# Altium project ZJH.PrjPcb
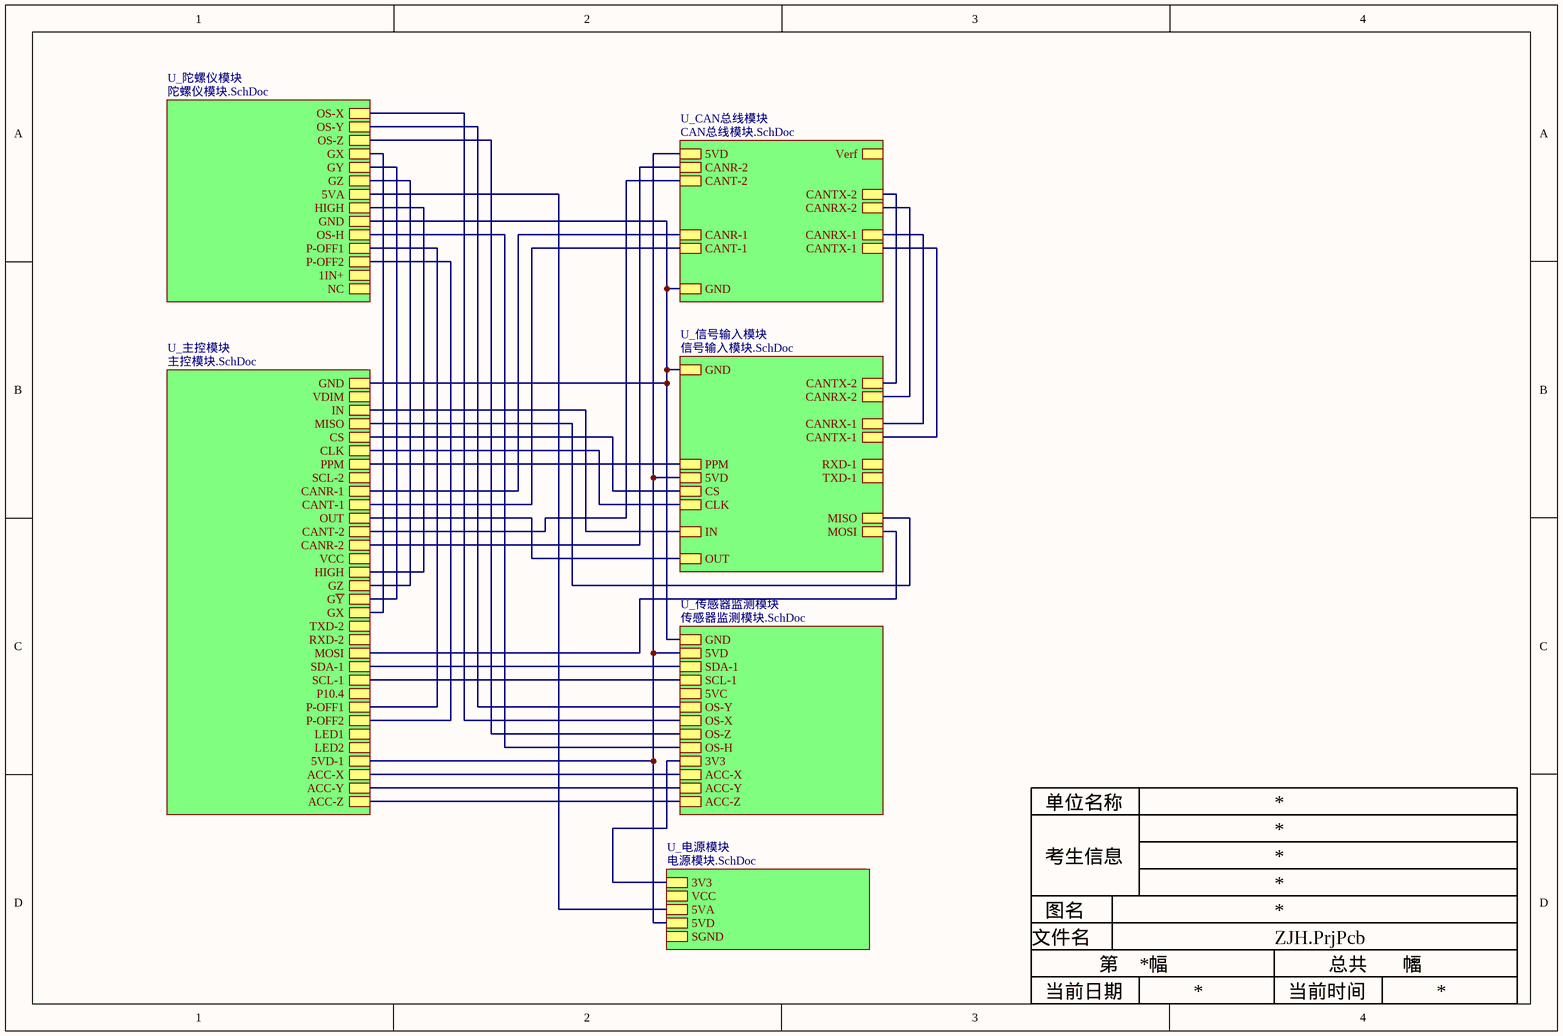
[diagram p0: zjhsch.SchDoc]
7 sheets, 110 parts. Net scope: hierarchical (ports join the sheet entries above them; power ports are global).
Board file: zjhpcb.PcbDoc
Sheets:
  zjhsch.SchDoc
    U_主控模块 = 主控模块.SchDoc
    U_传感器监测模块 = 传感器监测模块.SchDoc
    U_陀螺仪模块 = 陀螺仪模块.SchDoc
    U_CAN总线模块 = CAN总线模块.SchDoc
    U_信号输入模块 = 信号输入模块.SchDoc
    U_电源模块 = 电源模块.SchDoc

## Sheet zjhsch.SchDoc
size A4

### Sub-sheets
U_CAN总线模块 = CAN总线模块.SchDoc: 5VD, CANR-2, CANT-2, CANTX-2, CANRX-2, Verf, CANTX-1, CANRX-1, GND, CANR-1, CANT-1
U_主控模块 = 主控模块.SchDoc: 5VD-1, LED2, P10.4, SCL-1, SDA-1, LED1, P-OFF2, P-OFF1, RXD-2, MOSI, TXD-2, GX, G~{Y}, GZ, HIGH, ACC-X, ACC-Y, ACC-Z, VCC, CANT-1, CANT-2, OUT, CANR-1, SCL-2, PPM, CS, CLK, MISO, IN, GND, VDIM, CANR-2
U_传感器监测模块 = 传感器监测模块.SchDoc: GND, 5VD, SDA-1, SCL-1, 5VC, OS-Y, OS-X, OS-Z, OS-H, 3V3, ACC-Z, ACC-Y, ACC-X
U_信号输入模块 = 信号输入模块.SchDoc: OUT, MOSI, IN, MISO, CLK, CS, 5VD, PPM, TXD-1, RXD-1, CANTX-1, CANRX-1, CANRX-2, CANTX-2, GND
U_电源模块 = 电源模块.SchDoc: 3V3, VCC, 5VA, 5VD, SGND
U_陀螺仪模块 = 陀螺仪模块.SchDoc: 5VA, OS-X, 1IN+, GX, GZ, OS-Y, GY, HIGH, GND, OS-H, P-OFF1, P-OFF2, OS-Z, NC

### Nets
3V3: sheet U_传感器监测模块/3V3, sheet U_电源模块/3V3
5VA: sheet U_陀螺仪模块/5VA, sheet U_电源模块/5VA
5VD: sheet U_主控模块/5VD-1, sheet U_传感器监测模块/5VD, sheet U_CAN总线模块/5VD, sheet U_信号输入模块/5VD, sheet U_电源模块/5VD
GND: sheet U_主控模块/GND, sheet U_传感器监测模块/GND, sheet U_陀螺仪模块/GND, sheet U_CAN总线模块/GND, sheet U_信号输入模块/GND, sheet U_电源模块/SGND
VCC: sheet U_主控模块/VCC, sheet U_电源模块/VCC
ACC-X: sheet U_主控模块/ACC-X, sheet U_传感器监测模块/ACC-X
ACC-Y: sheet U_主控模块/ACC-Y, sheet U_传感器监测模块/ACC-Y
ACC-Z: sheet U_主控模块/ACC-Z, sheet U_传感器监测模块/ACC-Z
CANR-1: sheet U_主控模块/CANR-1, sheet U_CAN总线模块/CANR-1
CANR-2: sheet U_主控模块/CANR-2, sheet U_CAN总线模块/CANR-2
CANRX-1: sheet U_CAN总线模块/CANRX-1, sheet U_信号输入模块/CANRX-1
CANRX-2: sheet U_CAN总线模块/CANRX-2, sheet U_信号输入模块/CANRX-2
CANT-1: sheet U_主控模块/CANT-1, sheet U_CAN总线模块/CANT-1
CANT-2: sheet U_主控模块/CANT-2, sheet U_CAN总线模块/CANT-2
CANTX-1: sheet U_CAN总线模块/CANTX-1, sheet U_信号输入模块/CANTX-1
CANTX-2: sheet U_CAN总线模块/CANTX-2, sheet U_信号输入模块/CANTX-2
CLK: sheet U_主控模块/CLK, sheet U_信号输入模块/CLK
CS: sheet U_主控模块/CS, sheet U_信号输入模块/CS
GX: sheet U_主控模块/GX, sheet U_陀螺仪模块/GX
GY: sheet U_主控模块/G~{Y}, sheet U_陀螺仪模块/GY
GZ: sheet U_主控模块/GZ, sheet U_陀螺仪模块/GZ
High: sheet U_主控模块/HIGH, sheet U_陀螺仪模块/HIGH
IN: sheet U_主控模块/IN, sheet U_信号输入模块/IN
MISO: sheet U_主控模块/MISO, sheet U_信号输入模块/MISO
MOSI: sheet U_主控模块/MOSI, sheet U_信号输入模块/MOSI
OS-H: sheet U_传感器监测模块/OS-H, sheet U_陀螺仪模块/OS-H
OS-X: sheet U_传感器监测模块/OS-X, sheet U_陀螺仪模块/OS-X
OS-Y: sheet U_传感器监测模块/OS-Y, sheet U_陀螺仪模块/OS-Y
OS-Z: sheet U_传感器监测模块/OS-Z, sheet U_陀螺仪模块/OS-Z
OUT: sheet U_主控模块/OUT, sheet U_信号输入模块/OUT
P-OFF1: sheet U_主控模块/P-OFF1, sheet U_陀螺仪模块/P-OFF1
P-OFF2: sheet U_主控模块/P-OFF2, sheet U_陀螺仪模块/P-OFF2
PPM: sheet U_主控模块/PPM, sheet U_信号输入模块/PPM
SCL-1: sheet U_主控模块/SCL-1, sheet U_传感器监测模块/SCL-1
SDA-1: sheet U_主控模块/SDA-1, sheet U_传感器监测模块/SDA-1

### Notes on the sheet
- 单位名称
- 考生信息
- 图名
- 文件名
- 第      幅
- 总共       幅
- 当前日期
- 当前时间

## Sheet 主控模块.SchDoc
size A4
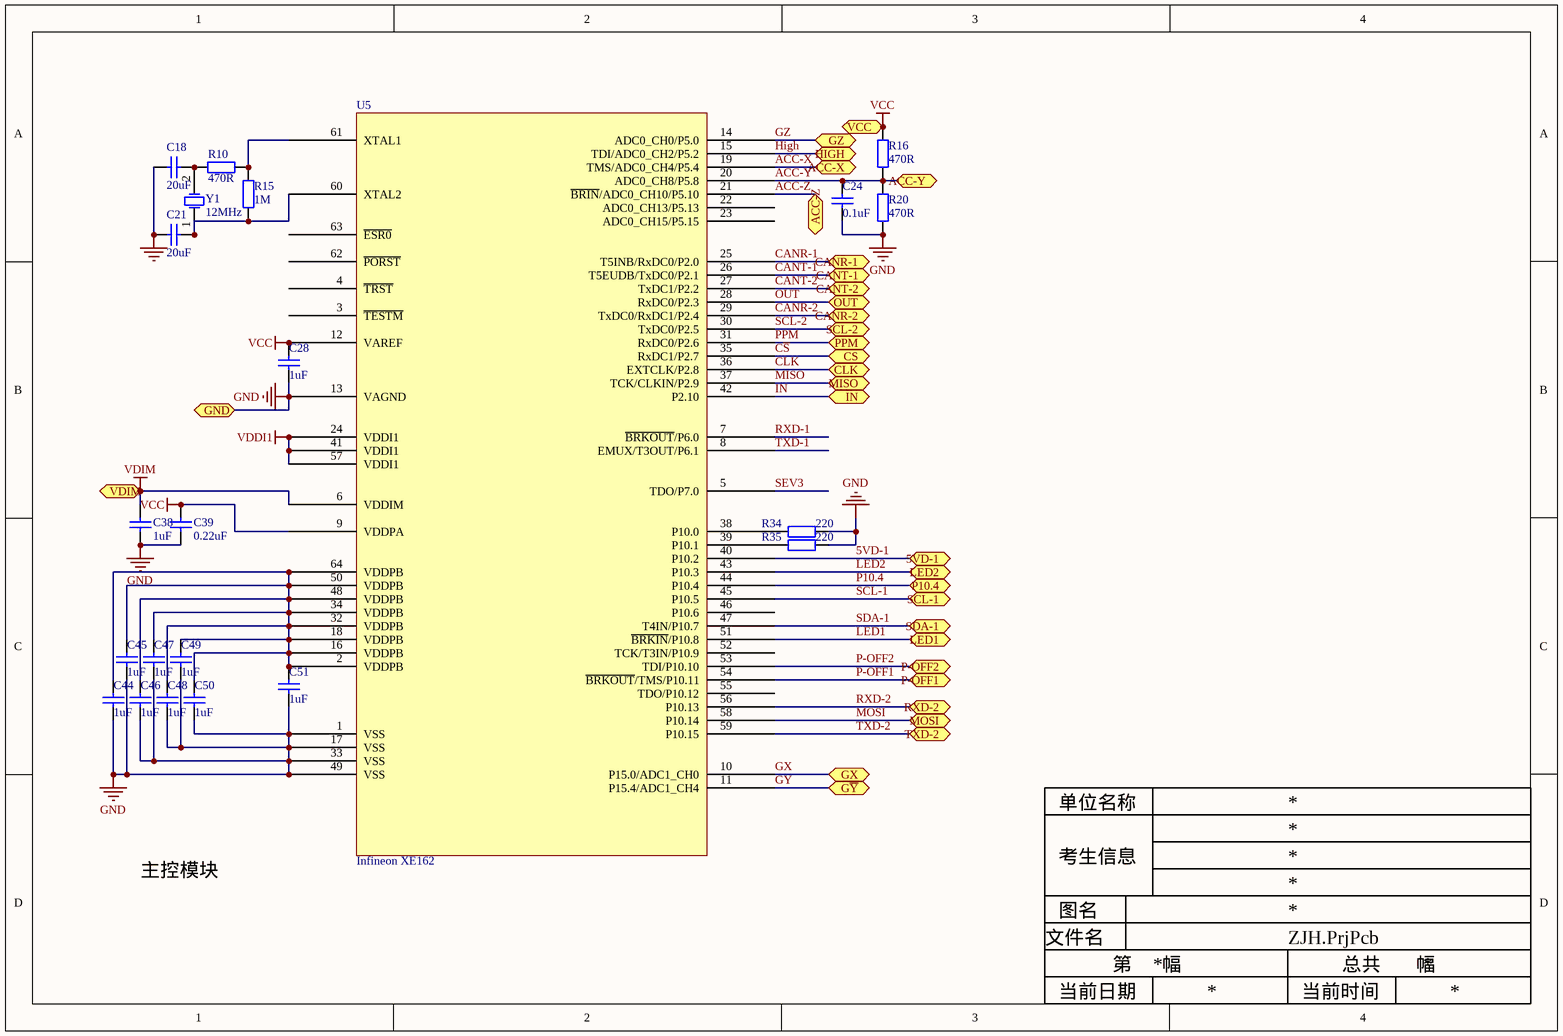
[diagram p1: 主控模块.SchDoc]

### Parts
C18  value 20uF  [RAD-0.3]  (hidden comment: Cap)
C21  value 20uF  [RAD-0.3]  (hidden comment: Cap)
C24  value 0.1uF  [RAD-0.3]  (hidden comment: Cap)
C28  value 1uF  [RAD-0.3]  (hidden comment: Cap)
C38  value 1uF  [RAD-0.3]  (hidden comment: Cap)
C39  value 0.22uF  [RAD-0.3]  (hidden comment: Cap)
C44  value 1uF  [RAD-0.3]  (hidden comment: Cap)
C45  value 1uF  [RAD-0.3]  (hidden comment: Cap)
C46  value 1uF  [RAD-0.3]  (hidden comment: Cap)
C47  value 1uF  [RAD-0.3]  (hidden comment: Cap)
C48  value 1uF  [RAD-0.3]  (hidden comment: Cap)
C49  value 1uF  [RAD-0.3]  (hidden comment: Cap)
C50  value 1uF  [RAD-0.3]  (hidden comment: Cap)
C51  value 1uF  [RAD-0.3]  (hidden comment: Cap)
R10  470R  [1608[0603]]
R15  1M  [1608[0603]]
R16  470R  [R0603]
R20  470R  [R0603]
R34  220  [R0603]
R35  220  [R0603]
U5  Infineon XE162  [Infineon XE162]
Y1  12MHz  [R38]

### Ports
5VD-1, ACC-X, ACC-Y, ACC-Z, CANR-1, CANR-2, CANT-1, CANT-2, CLK, CS, GND, GX, GZ, G~{Y}, HIGH, IN, LED1, LED2, MISO, MOSI, OUT, P10.4, P-OFF1, P-OFF2, PPM, RXD-2, SCL-1, SCL-2, SDA-1, TXD-2, VCC, VDIM

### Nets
5VD-1: U5.40(P10.2) ; port 5VD-1  [project net 5VD]
GND: C18.2 C21.2 C24.1 C28.1 C38.2 C39.2 C44.1 C45.1 C46.1 C47.1 C48.1 C49.1 C50.1 C51.1 R20.1 R34.1 R35.1 U5.1(VSS) U5.13(VAGND) U5.17(VSS) U5.33(VSS) U5.49(VSS) ; port GND
VCC: C28.2 C39.1 R16.2 U5.9(VDDPA) U5.12(VAREF) ; port VCC
VDDI1: U5.24(VDDI1) U5.41(VDDI1) U5.57(VDDI1)
VDIM: C38.1 U5.6(VDDIM) ; port VDIM
ACC-X: U5.19(TMS/ADC0_CH4/P5.4) ; port ACC-X
ACC-Y: C24.2 R16.1 R20.2 U5.20(ADC0_CH8/P5.8) ; port ACC-Y
ACC-Z: U5.21(~{BRIN}/ADC0_CH10/P5.10) ; port ACC-Z
CANR-1: U5.25(T5INB/RxDC0/P2.0) ; port CANR-1
CANR-2: U5.29(TxDC0/RxDC1/P2.4) ; port CANR-2
CANT-1: U5.26(T5EUDB/TxDC0/P2.1) ; port CANT-1
CANT-2: U5.27(TxDC1/P2.2) ; port CANT-2
CLK: U5.36(EXTCLK/P2.8) ; port CLK
C~{S}: U5.35(RxDC1/P2.7) ; port CS  [project net CS]
GX: U5.10(P15.0/ADC1_CH0) ; port GX
GY: U5.11(P15.4/ADC1_CH4) ; port G~{Y}
GZ: U5.14(ADC0_CH0/P5.0) ; port GZ
High: U5.15(TDI/ADC0_CH2/P5.2) ; port HIGH
IN: U5.42(P2.10) ; port IN
LED1: U5.51(~{BRKIN}/P10.8) ; port LED1
LED2: U5.43(P10.3) ; port LED2
MISO: U5.37(TCK/CLKIN/P2.9) ; port MISO
MOSI: U5.58(P10.14) ; port MOSI
OUT: U5.28(RxDC0/P2.3) ; port OUT
P10.4: U5.44(P10.4) ; port P10.4
P-OFF1: U5.54(~{BRKOUT}/TMS/P10.11) ; port P-OFF1
P-OFF2: U5.53(TDI/P10.10) ; port P-OFF2
PPM: U5.31(RxDC0/P2.6) ; port PPM
RXD-1: U5.7(~{BRKOUT}/P6.0)
RXD-2: U5.56(P10.13) ; port RXD-2
SCL-1: U5.45(P10.5) ; port SCL-1
SCL-2: U5.30(TxDC0/P2.5) ; port SCL-2
SDA-1: U5.47(T4IN/P10.7) ; port SDA-1
SEV3: U5.5(TDO/P7.0)
TXD-1: U5.8(EMUX/T3OUT/P6.1)
TXD-2: U5.59(P10.15) ; port TXD-2
NetC18_1: C18.1 R10.2 Y1.2(OSC2)
NetC21_1: C21.1 R15.1 U5.60(XTAL2) Y1.1(OSC1)
NetC44_2: C44.2 C45.2 C46.2 C47.2 C48.2 C49.2 C50.2 C51.2 U5.2(VDDPB) U5.16(VDDPB) U5.18(VDDPB) U5.32(VDDPB) U5.34(VDDPB) U5.48(VDDPB) U5.50(VDDPB) U5.64(VDDPB)
NetR10_1: R10.1 R15.2 U5.61(XTAL1)
NetR34_2: R34.2 U5.38(P10.0)
NetR35_2: R35.2 U5.39(P10.1)

Not connected (* = marked no-connect by the designer): U5 3(~{TESTM}) 4(~{TRST}) 22(ADC0_CH13/P5.13) 23(ADC0_CH15/P5.15) 46(P10.6) 52(TCK/T3IN/P10.9) 55(TDO/P10.12) 62(~{PORST}) 63(~{ESR0})

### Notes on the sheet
- 单位名称
- 考生信息
- 图名
- 文件名
- 第      幅
- 总共       幅
- 当前日期
- 当前时间
- Labels drawn without touching a wire or pin: 主控模块

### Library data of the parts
C18 C21 C24 C28 C38 C39 C44-C51 = Cap: Capacitor
R10 R15 = R0805
R16 R20 R34 R35 = R0603
Y1 = XTAL: Crystal Oscillator

## Sheet 传感器监测模块.SchDoc
size A4
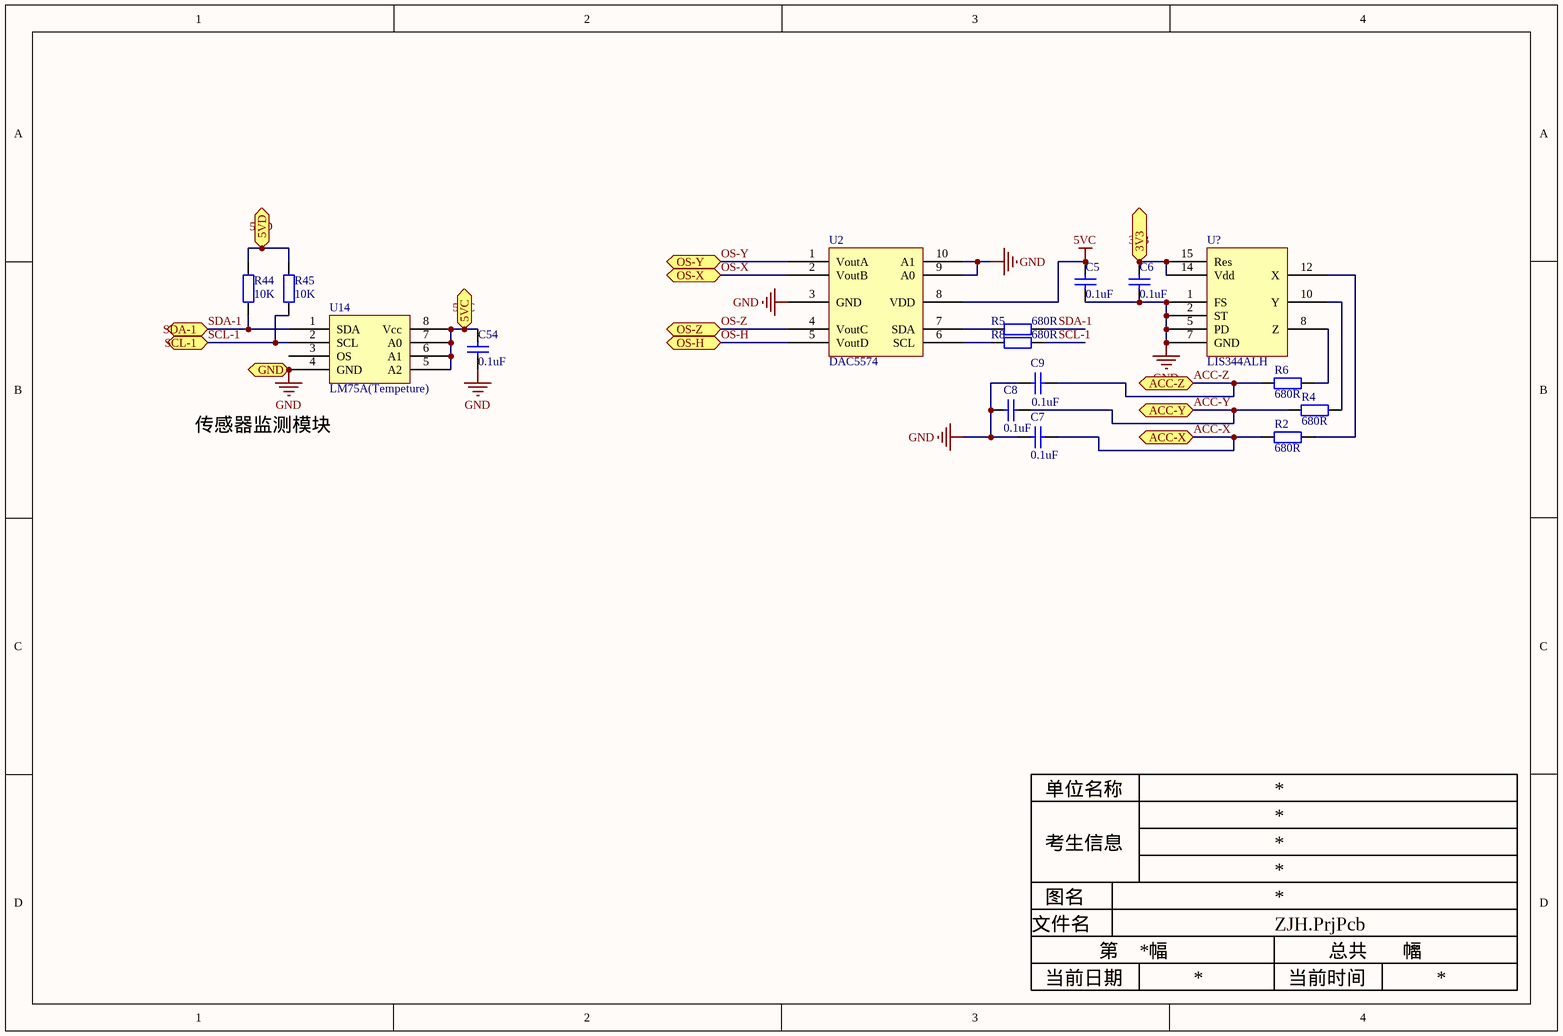
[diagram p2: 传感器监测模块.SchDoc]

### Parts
C5  value 0.1uF  [RAD-0.3]  (hidden comment: Cap)
C6  value 0.1uF  [RAD-0.3]  (hidden comment: Cap)
C7  value 0.1uF  [RAD-0.3]  (hidden comment: Cap)
C8  value 0.1uF  [RAD-0.3]  (hidden comment: Cap)
C9  value 0.1uF  [RAD-0.3]  (hidden comment: Cap)
C54  value 0.1uF  [RAD-0.3]  (hidden comment: Cap)
R2  680R  [R0603]
R4  680R  [R0603]
R5  680R  [R0603]
R6  680R  [R0603]
R8  680R  [R0603]
R44  10K  [1608[0603]]
R45  10K  [1608[0603]]
U2  DAC5574
U14  LM75A(Tempeture)  [LM75A]
U?  LIS344ALH  [LIS344ALH(Acc)]

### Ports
3V3, 5VC, 5VD, ACC-X, ACC-Y, ACC-Z, GND, OS-H, OS-X, OS-Y, OS-Z, SCL-1, SDA-1

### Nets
3V3: C6.2 U?.14(Vdd) U?.15(Res) ; port 3V3
5VC: C5.2 C54.2 U2.8(VDD) U14.5(A2) U14.6(A1) U14.7(A0) U14.8(Vcc) ; port 5VC
5VD: R44.2 R45.2 ; port 5VD
GND: C5.1 C6.1 C7.2 C8.2 C9.2 C54.1 U2.3(GND) U2.9(A0) U2.10(A1) U14.4(GND) U?.1(FS) U?.2(ST) U?.5(PD) U?.7(GND) ; port GND
ACC-X: C7.1 R2.2 ; port ACC-X
ACC-Y: C8.1 R4.2 ; port ACC-Y
ACC-Z: C9.1 R6.2 ; port ACC-Z
OS-H: U2.5(VoutD) ; port OS-H
OS-X: U2.2(VoutB) ; port OS-X
OS-Y: U2.1(VoutA) ; port OS-Y
OS-Z: U2.4(VoutC) ; port OS-Z
SCL-1: R8.2 R45.1 U14.2(SCL) ; port SCL-1
SDA-1: R5.2 R44.1 U14.1(SDA) ; port SDA-1
NetR2_1: R2.1 U?.12(X)
NetR4_1: R4.1 U?.10(Y)
NetR5_1: R5.1 U2.7(SDA)
NetR6_1: R6.1 U?.8(Z)
NetR8_1: R8.1 U2.6(SCL)

Not connected (* = marked no-connect by the designer): U14 3(OS)

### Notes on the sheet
- 单位名称
- 考生信息
- 图名
- 文件名
- 当前日期
- 第      幅
- 当前时间
- 总共       幅
- Labels drawn without touching a wire or pin: 传感器监测模块

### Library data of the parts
C5-C9 C54 = Cap: Capacitor
R2 R4-R6 R8 = R0603
R44 R45 = R0805
U? = ACC(LIS344ALH)

## Sheet 陀螺仪模块.SchDoc
size A4
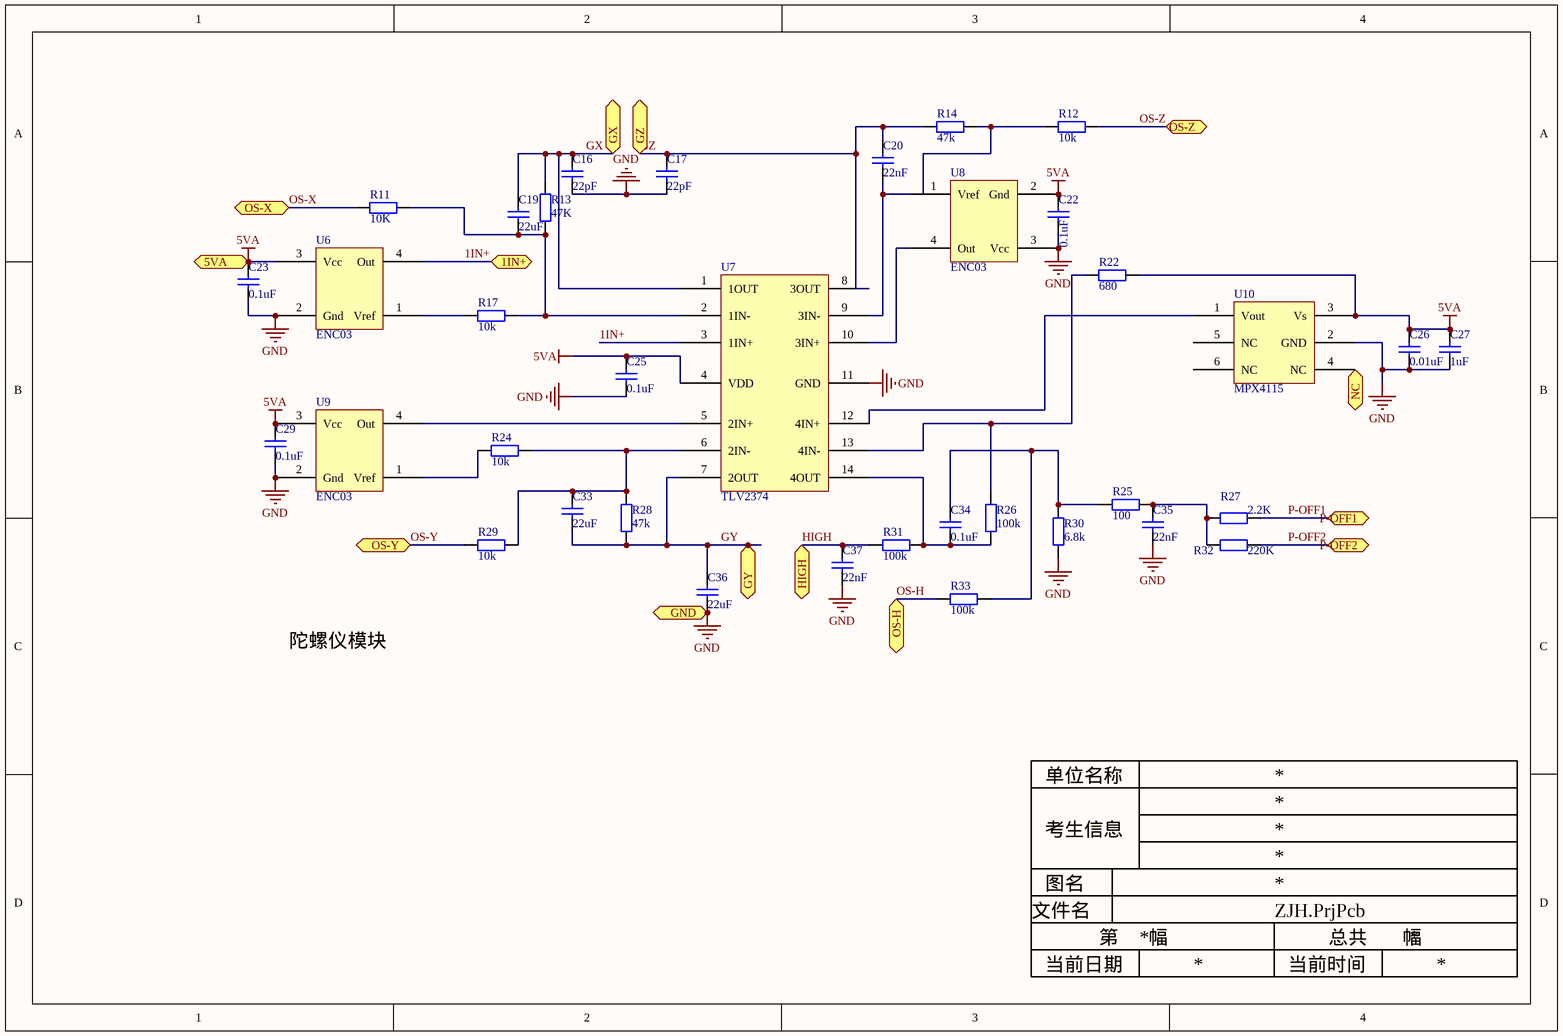
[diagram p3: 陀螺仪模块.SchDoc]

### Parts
C16  value 22pF  [RAD-0.3]  (hidden comment: Cap)
C17  value 22pF  [RAD-0.3]  (hidden comment: Cap)
C19  value 22uF  [RAD-0.3]  (hidden comment: Cap)
C20  value 22nF  [RAD-0.3]  (hidden comment: Cap)
C22  value 0.1uF  [RAD-0.3]  (hidden comment: Cap)
C23  value 0.1uF  [RAD-0.3]  (hidden comment: Cap)
C25  value 0.1uF  [RAD-0.3]  (hidden comment: Cap)
C26  value 0.01uF  [RAD-0.3]  (hidden comment: Cap)
C27  value 1uF  [RAD-0.3]  (hidden comment: Cap)
C29  value 0.1uF  [RAD-0.3]  (hidden comment: Cap)
C33  value 22uF  [RAD-0.3]  (hidden comment: Cap)
C34  value 0.1uF  [RAD-0.3]  (hidden comment: Cap)
C35  value 22nF  [RAD-0.3]  (hidden comment: Cap)
C36  value 22uF  [RAD-0.3]  (hidden comment: Cap)
C37  value 22nF  [RAD-0.3]  (hidden comment: Cap)
R11  10K  [R0603]
R12  10k  [R0603]
R13  47K  [R0603]
R14  47k  [R0603]
R17  10k  [R0603]
R22  680  [R0603]
R24  10k  [R0603]
R25  100  [R0603]
R26  100k  [R0603]
R27  2.2K  [R0603]
R28  47k  [R0603]
R29  10k  [R0603]
R30  6.8k  [R0603]
R31  100k  [R0603]
R32  220K  [R0603]
R33  100k  [R0603]
U6  ENC03  [ENC03]
U7  TLV2374  [TLV 2374]
U8  ENC03  [ENC03]
U9  ENC03  [ENC03]
U10  MPX4115  [MPX4115]

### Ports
1IN+, 5VA, GND, GX, GY, GZ, HIGH, NC, OS-H, OS-X, OS-Y, OS-Z, P-OFF1, P-OFF2

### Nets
5VA: C22.2 C23.2 C25.2 C26.2 C27.2 C29.2 R22.1 U6.3(Vcc) U7.4(VDD) U8.2(Gnd) U9.3(Vcc) U10.3(Vs) ; port 5VA
GND: C16.1 C17.1 C22.1 C23.1 C25.1 C26.1 C27.1 C29.1 C35.1 C36.1 C37.1 R30.1 U6.2(Gnd) U7.11(GND) U8.3(Vcc) U9.2(Gnd) U10.2(GND) ; port GND
1IN+: U6.4(Out) U7.3(1IN+) ; port 1IN+
GX: C16.2 C19.2 R13.1 U7.1(1OUT) ; port GX
GY: C33.1 C36.2 R28.2 U7.7(2OUT) ; port GY
GZ: C17.2 C20.2 R14.1 U7.8(3OUT) ; port GZ
High: C37.2 R31.1 ; port HIGH
OS-H: R33.1 ; port OS-H
OS-X: R11.2 ; port OS-X
OS-Y: R29.2 ; port OS-Y
OS-Z: R12.2 ; port OS-Z
P-OFF1: R27.1 ; port P-OFF1
P-OFF2: R32.1 ; port P-OFF2
NetC19_1: C19.1 R11.1 R13.2 R17.1 U7.2(1IN-)
NetC20_1: C20.1 U7.9(3IN-) U8.1(Vref)
NetC33_2: C33.2 R24.1 R28.1 R29.1 U7.6(2IN-)
NetC34_1: C34.1 R26.1 R31.2 U7.14(4OUT)
NetC34_2: C34.2 R25.2 R30.2 R33.2
NetC35_2: C35.2 R25.1 R27.2 R32.2
NetR12_1: R12.1 R14.2
NetR17_2: R17.2 U6.1(Vref)
NetR22_2: R22.2 R26.2 U7.13(4IN-)
NetR24_2: R24.2 U9.1(Vref)
NetU7_5: U7.5(2IN+) U9.4(Out)
NetU7_10: U7.10(3IN+) U8.4(Out)
NetU7_12: U7.12(4IN+) U10.1(Vout)
NetU10_4: U10.4(NC) ; port NC

Not connected (* = marked no-connect by the designer): U10 5(NC) 6(NC)

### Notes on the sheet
- 单位名称
- 考生信息
- 文件名
- 图名
- 当前日期
- 第      幅
- 当前时间
- 总共       幅
- Labels drawn without touching a wire or pin: 陀螺仪模块

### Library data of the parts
C16 C17 C19 C20 C22 C23 C25-C27 C29 C33-C37 = Cap: Capacitor
R11-R14 R17 R22 R24-R33 = R0603

## Sheet CAN总线模块.SchDoc
size A4
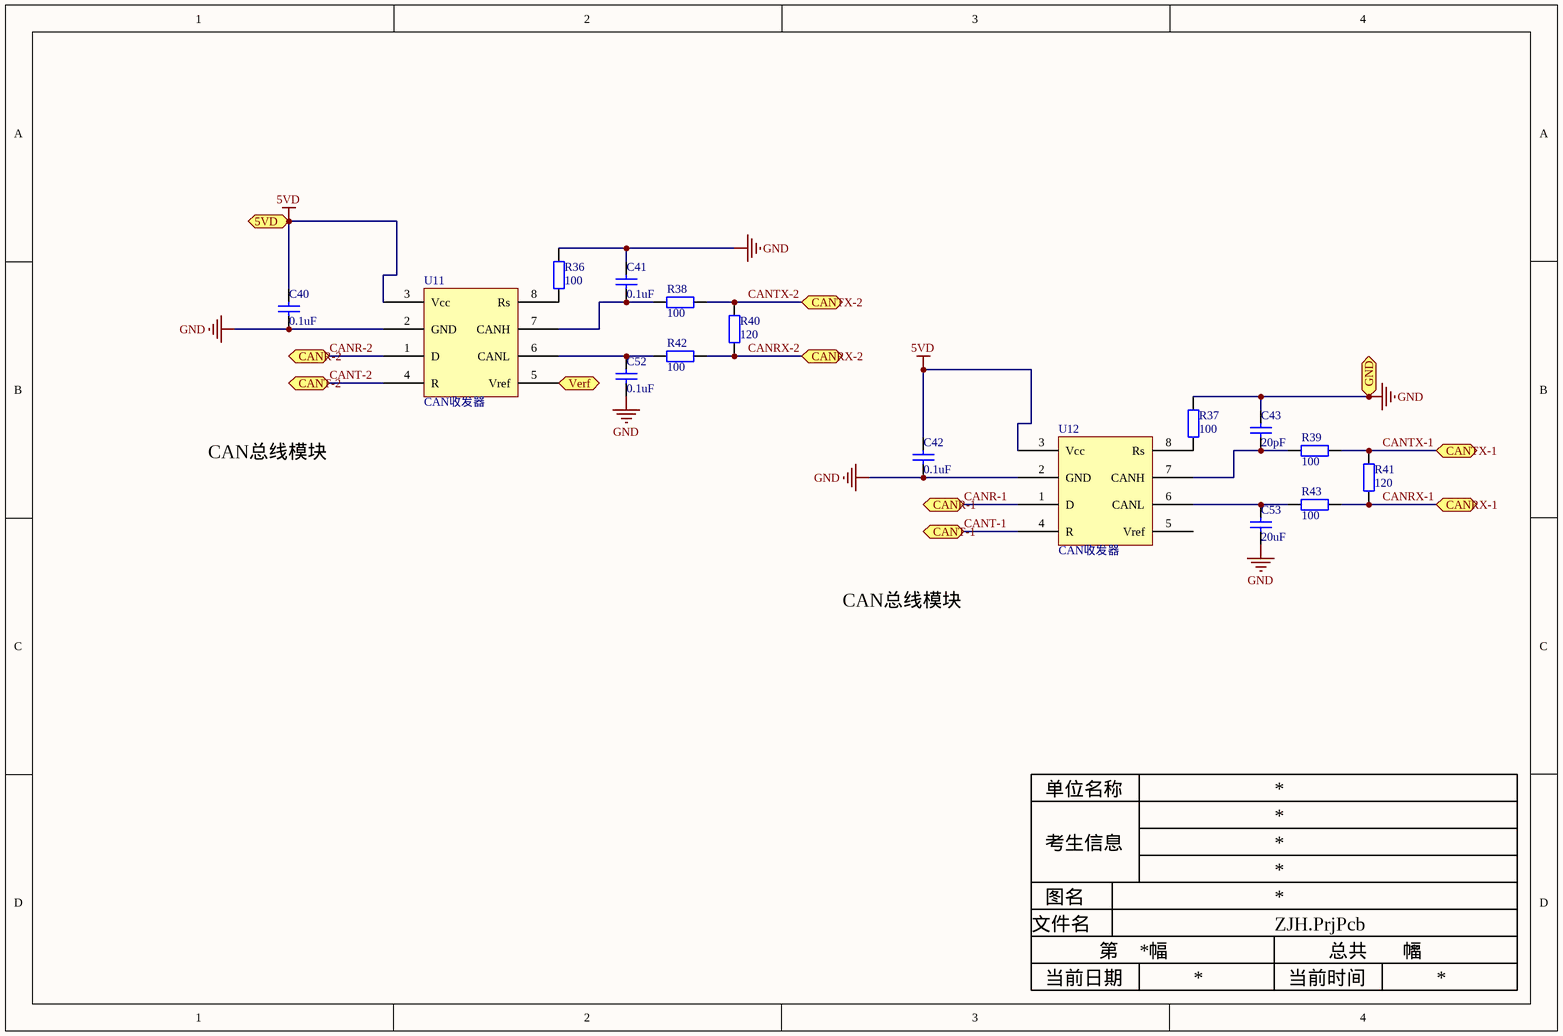
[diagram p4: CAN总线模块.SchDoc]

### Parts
C40  value 0.1uF  [RAD-0.3]  (hidden comment: Cap)
C41  value 0.1uF  [RAD-0.3]  (hidden comment: Cap)
C42  value 0.1uF  [RAD-0.3]  (hidden comment: Cap)
C43  value 20pF  [RAD-0.3]  (hidden comment: Cap)
C52  value 0.1uF  [RAD-0.3]  (hidden comment: Cap)
C53  value 20uF  [RAD-0.3]  (hidden comment: Cap)
R36  100  [R0603]
R37  100  [R0603]
R38  100  [R0603]
R39  100  [R0603]
R40  120  [R0603]
R41  120  [R0603]
R42  100  [R0603]
R43  100  [R0603]
U11  CAN收发器  [CAN]
U12  CAN收发器  [CAN]

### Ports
5VD, CANR-1, CANR-2, CANRX-1, CANRX-2, CANT-1, CANT-2, CANTX-1, CANTX-2, GND, Verf

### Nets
5VD: C40.2 C42.2 U11.3(Vcc) U12.3(Vcc) ; port 5VD
GND: C40.1 C41.2 C42.1 C43.2 C52.1 C53.1 R36.2 R37.2 U11.2(GND) U12.2(GND) ; port GND
CANR-1: U12.1(D) ; port CANR-1
CANR-2: U11.1(D) ; port CANR-2
CANRX-1: R41.2 R43.1 ; port CANRX-1
CANRX-2: R40.2 R42.1 ; port CANRX-2
CANT-1: U12.4(R) ; port CANT-1
CANT-2: U11.4(R) ; port CANT-2
CANTX-1: R39.1 R41.1 ; port CANTX-1
CANTX-2: R38.1 R40.1 ; port CANTX-2
NetC41_1: C41.1 R38.2 U11.7(CANH)
NetC43_1: C43.1 R39.2 U12.7(CANH)
NetC52_2: C52.2 R42.2 U11.6(CANL)
NetC53_2: C53.2 R43.2 U12.6(CANL)
NetR36_1: R36.1 U11.8(Rs)
NetR37_1: R37.1 U12.8(Rs)
NetU11_5: U11.5(Vref) ; port Verf

Not connected (* = marked no-connect by the designer): U12 5(Vref)

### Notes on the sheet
- 单位名称
- 考生信息
- 图名
- 文件名
- 当前日期
- 第      幅
- 当前时间
- 总共       幅
- Labels drawn without touching a wire or pin: CAN总线模块

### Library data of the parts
C40-C43 C52 C53 = Cap: Capacitor
R36-R43 = R0603
U11 U12 = CAN

## Sheet 信号输入模块.SchDoc
size A4
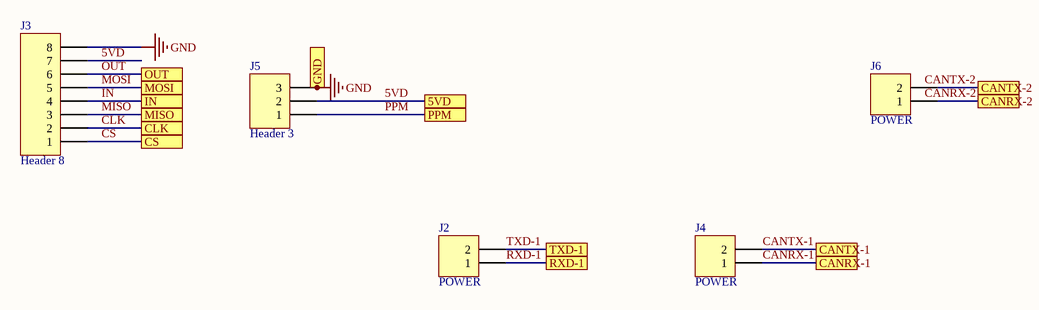
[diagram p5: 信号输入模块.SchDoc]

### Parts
J2  POWER  [HDR1X2]
J3  Header 8  [HDR1X8]
J4  POWER  [HDR1X2]
J5  Header 3  [HDR1X3]
J6  POWER  [HDR1X2]

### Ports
5VD, CANRX-1, CANRX-2, CANTX-1, CANTX-2, CLK, CS, GND, IN, MISO, MOSI, OUT, PPM, RXD-1, TXD-1

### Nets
5VD: J3.7 J5.2 ; port 5VD
GND: J3.8 J5.3 ; port GND
CANRX-1: J4.1 ; port CANRX-1
CANRX-2: J6.1 ; port CANRX-2
CANTX-1: J4.2 ; port CANTX-1
CANTX-2: J6.2 ; port CANTX-2
CLK: J3.2 ; port CLK
CS: J3.1 ; port CS
IN: J3.4 ; port IN
MISO: J3.3 ; port MISO
MOSI: J3.5 ; port MOSI
OUT: J3.6 ; port OUT
PPM: J5.1 ; port PPM
RXD-1: J2.1 ; port RXD-1
TXD-1: J2.2 ; port TXD-1

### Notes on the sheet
- Labels drawn without touching a wire or pin: CANRX-2, CANTX-2

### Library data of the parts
J2 J4 J6 = Header 2: Header, 2-Pin
J3 = Header 8: Header, 8-Pin
J5 = Header 3: Header, 3-Pin

## Sheet 电源模块.SchDoc
size A4
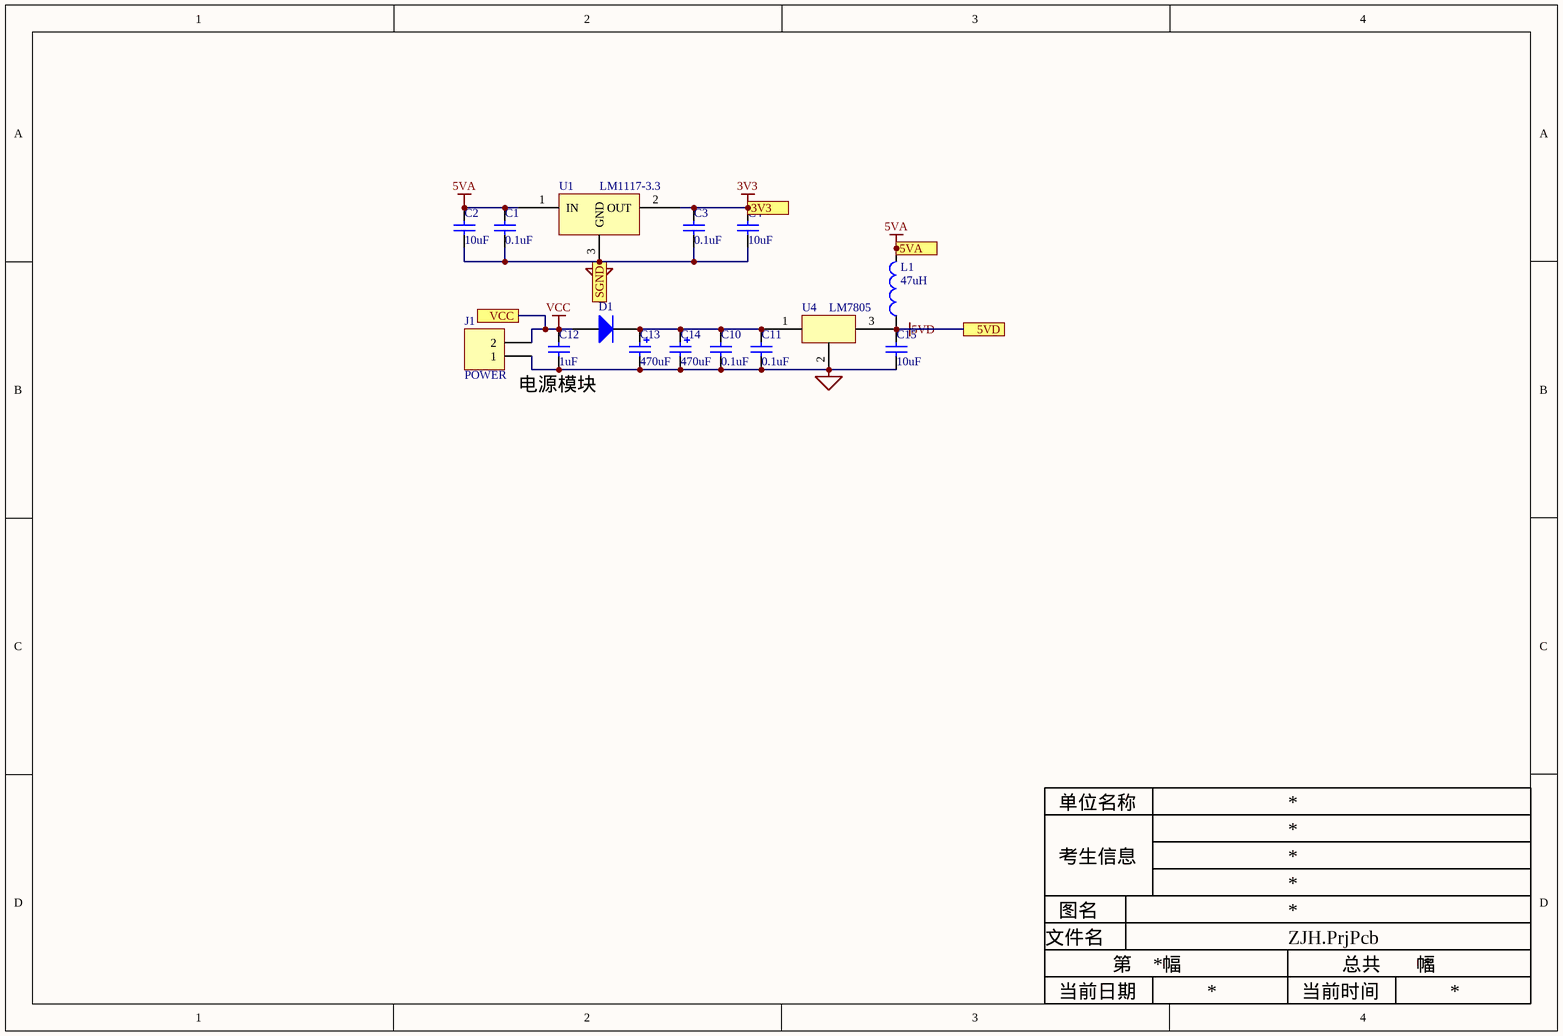
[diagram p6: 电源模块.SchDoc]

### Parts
C1  value 0.1uF  [RAD-0.3]  (hidden comment: Cap)
C2  value 10uF  [RAD-0.3]  (hidden comment: Cap)
C3  value 0.1uF  [RAD-0.3]  (hidden comment: Cap)
C4  value 10uF  [RAD-0.3]  (hidden comment: Cap)
C10  value 0.1uF  [RAD-0.3]  (hidden comment: Cap)
C11  value 0.1uF  [RAD-0.3]  (hidden comment: Cap)
C12  value 1uF  [RAD-0.3]  (hidden comment: Cap)
C13  value 470uF  [POLAR0.8]  (hidden comment: Cap Pol2)
C14  value 470uF  [POLAR0.8]  (hidden comment: Cap Pol2)
C15  value 10uF  [RAD-0.3]  (hidden comment: Cap)
D1  Diode  [SMC]  (value not drawn)
J1  POWER  [HDR1X2]
L1  47uH  [DIODE_SMC]
U1  LM1117-3.3  [LM1117-3.3]
U4  LM7805  [TO-220AB]

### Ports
3V3, 5VA, 5VD, SGND, VCC

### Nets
3V3: C3.2 C4.2 U1.2(OUT) ; port 3V3
5VA: C1.2 C2.2 L1.2 U1.1(IN) ; port 5VA
5VD: C15.2 L1.1 U4.3 ; port 5VD
GND: C1.1 C2.1 C3.1 C4.1 C10.1 C11.1 C12.1 C13.2 C14.2 C15.1 J1.1 U1.3(GND) U4.2 ; port SGND
VCC: C12.2 D1.1(A) J1.2 ; port VCC
NetC10_2: C10.2 C11.2 C13.1 C14.1 D1.2(K) U4.1

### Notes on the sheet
- 单位名称
- 考生信息
- 图名
- 文件名
- 第      幅
- 总共       幅
- 当前日期
- 当前时间
- Labels drawn without touching a wire or pin: 电源模块

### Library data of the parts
C1-C4 C10-C12 C15 = Cap: Capacitor
C13 C14 = Cap Pol2: Polarized Capacitor (Axial)
D1 = Diode: Default Diode
J1 = Header 2: Header, 2-Pin
L1 = Inductor47uH
U4 = 7805

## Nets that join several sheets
3V3: 传感器监测模块 (C6.2 U?.14 U?.15), 电源模块 (C3.2 C4.2 U1.2)
5VA: 陀螺仪模块 (12 pins), 电源模块 (C1.2 C2.2 L1.2 U1.1)
5VD: 主控模块 (U5.40), 传感器监测模块 (R44.2 R45.2), CAN总线模块 (C40.2 C42.2 U11.3 U12.3), 信号输入模块 (J3.7 J5.2), 电源模块 (C15.2 L1.1 U4.3)
GND: 主控模块 (22 pins), 传感器监测模块 (14 pins), 陀螺仪模块 (17 pins), CAN总线模块 (10 pins), 信号输入模块 (J3.8 J5.3), 电源模块 (13 pins)
VCC: 主控模块 (5 pins), 电源模块 (C12.2 D1.1 J1.2)
ACC-X: 主控模块 (U5.19), 传感器监测模块 (C7.1 R2.2)
ACC-Y: 主控模块 (C24.2 R16.1 R20.2 U5.20), 传感器监测模块 (C8.1 R4.2)
ACC-Z: 主控模块 (U5.21), 传感器监测模块 (C9.1 R6.2)
CANR-1: 主控模块 (U5.25), CAN总线模块 (U12.1)
CANR-2: 主控模块 (U5.29), CAN总线模块 (U11.1)
CANRX-1: CAN总线模块 (R41.2 R43.1), 信号输入模块 (J4.1)
CANRX-2: CAN总线模块 (R40.2 R42.1), 信号输入模块 (J6.1)
CANT-1: 主控模块 (U5.26), CAN总线模块 (U12.4)
CANT-2: 主控模块 (U5.27), CAN总线模块 (U11.4)
CANTX-1: CAN总线模块 (R39.1 R41.1), 信号输入模块 (J4.2)
CANTX-2: CAN总线模块 (R38.1 R40.1), 信号输入模块 (J6.2)
CLK: 主控模块 (U5.36), 信号输入模块 (J3.2)
CS: 主控模块 (U5.35), 信号输入模块 (J3.1)
GX: 主控模块 (U5.10), 陀螺仪模块 (C16.2 C19.2 R13.1 U7.1)
GY: 主控模块 (U5.11), 陀螺仪模块 (C33.1 C36.2 R28.2 U7.7)
GZ: 主控模块 (U5.14), 陀螺仪模块 (C17.2 C20.2 R14.1 U7.8)
High: 主控模块 (U5.15), 陀螺仪模块 (C37.2 R31.1)
IN: 主控模块 (U5.42), 信号输入模块 (J3.4)
MISO: 主控模块 (U5.37), 信号输入模块 (J3.3)
MOSI: 主控模块 (U5.58), 信号输入模块 (J3.5)
OS-H: 传感器监测模块 (U2.5), 陀螺仪模块 (R33.1)
OS-X: 传感器监测模块 (U2.2), 陀螺仪模块 (R11.2)
OS-Y: 传感器监测模块 (U2.1), 陀螺仪模块 (R29.2)
OS-Z: 传感器监测模块 (U2.4), 陀螺仪模块 (R12.2)
OUT: 主控模块 (U5.28), 信号输入模块 (J3.6)
P-OFF1: 主控模块 (U5.54), 陀螺仪模块 (R27.1)
P-OFF2: 主控模块 (U5.53), 陀螺仪模块 (R32.1)
PPM: 主控模块 (U5.31), 信号输入模块 (J5.1)
SCL-1: 主控模块 (U5.45), 传感器监测模块 (R8.2 R45.1 U14.2)
SDA-1: 主控模块 (U5.47), 传感器监测模块 (R5.2 R44.1 U14.1)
